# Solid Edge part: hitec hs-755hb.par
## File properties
Author: nakano
Template: iso metric part.par
Last saved by: nakano
Revision: 4
Application: Solid Edge
Density: 1087.51020887201 kg/m^3
Accuracy: 0.990
Username: nakano
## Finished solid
Body 1: solid body, 223 faces, 538 edges, 328 vertices, 4 internal voids.
  Faces by surface: plane 145, cylinder 46, cone 24, sphere 4, torus 4
  Edges by curve: line 314, circle 192, spline 32
Bounding box of the edges (mm; curved faces can reach further): 74.300 x 52.210 x 28.850, from (-51.9598, -28.1067, 59.875) to (22.3402, 24.1034, 88.725).
Cylindrical faces by radius (mm): R0.8 x4, R0.9 x4, R1 x6, R1.25 x1, R1.6 x4, R2 x16, R2.23 x1, R2.2479 x4, R5.275 x1, R5.485 x1, R6.275 x1, R6.96 x1, R12.7 x1, R13.7 x1
Conical faces (half-angle, radius in mm at the cone's reference point): 4 deg R0.3243 x16, 59 deg R0.9 x4, 72 deg R3077.6835 x4
Toroidal faces (ring radius, tube radius in mm): R1.1 r0.3 x4
Spherical faces by radius (mm): R2.5 x4
Planar faces by outward normal: +x 19, +y 19, +z 20, -x 20, -y 23, -z 20, oblique 24
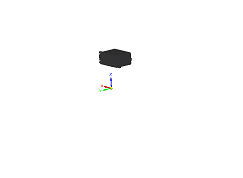
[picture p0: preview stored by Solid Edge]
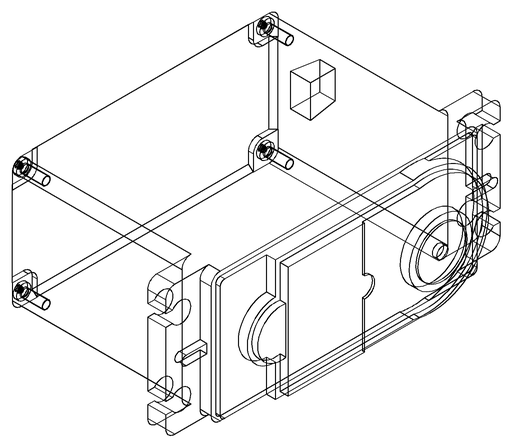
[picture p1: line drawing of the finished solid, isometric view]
